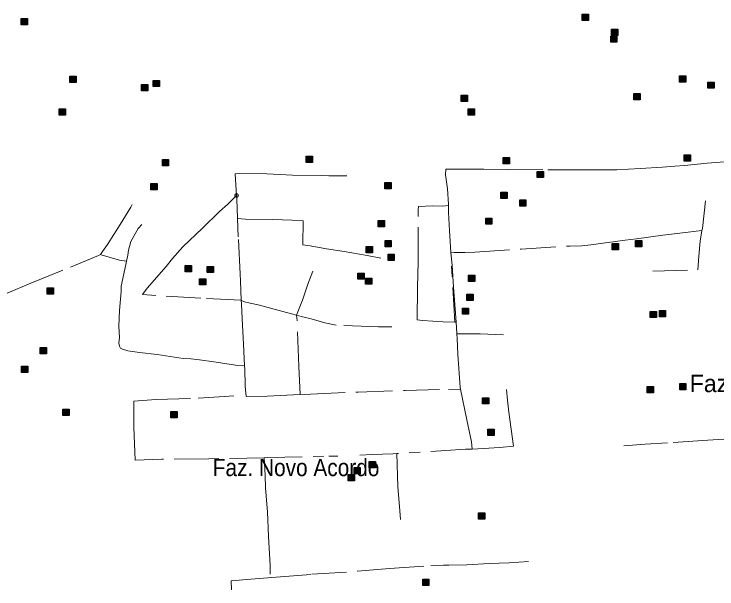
# Model space of a CAD drawing. Extents: x 393.5 to 446.9, y 8064.8 to 8120.4.
# Drawn here: x 418.49 to 425, y 8070.3 to 8075.61 of the extents above; entities that cross this region are included whole.
import ezdxf

# ---------------------------------------------------------------- set-up
doc = ezdxf.new("R2010")
doc.units = 0
doc.header["$LTSCALE"] = 0.064
doc.header["$PDMODE"] = 32
doc.header["$PDSIZE"] = 0.032
doc.linetypes.add('DOT_DASHED', pattern=[7.7, 5, -1.2, 0.3, -1.2])
doc.layers.add('2', color=7, linetype='Continuous', lineweight=25)
doc.layers.add('22', color=7, linetype='DOT_DASHED', lineweight=13)
doc.layers.add('61', color=7, linetype='Continuous')

msp = doc.modelspace()

# ---------------------------------------------------------------- hatches: boundary and pattern name
at = {"layer": '2'}
for points in [[(423.7495, 8075.6148), (423.8075, 8075.6148), (423.8075, 8075.5568), (423.7495, 8075.5568)], [(418.5591, 8075.573), (418.6171, 8075.573), (418.6171, 8075.515), (418.5591, 8075.515)], [(424.0194, 8075.4754), (424.0774, 8075.4754), (424.0774, 8075.4174), (424.0194, 8075.4174)], [(424.0124, 8075.4115), (424.0704, 8075.4115), (424.0704, 8075.3535), (424.0124, 8075.3535)], [(419.0076, 8075.0404), (419.0656, 8075.0404), (419.0656, 8074.9824), (419.0076, 8074.9824)], [(424.6491, 8075.0438), (424.7071, 8075.0438), (424.7071, 8074.9858), (424.6491, 8074.9858)], [(419.6731, 8074.9643), (419.7311, 8074.9643), (419.7311, 8074.9063), (419.6731, 8074.9063)], [(419.7799, 8075.0016), (419.8379, 8075.0016), (419.8379, 8074.9436), (419.7799, 8074.9436)], [(424.9126, 8074.9862), (424.9706, 8074.9862), (424.9706, 8074.9282), (424.9126, 8074.9282)], [(422.6299, 8074.8644), (422.6879, 8074.8644), (422.6879, 8074.8064), (422.6299, 8074.8064)], [(424.2267, 8074.8811), (424.2847, 8074.8811), (424.2847, 8074.8231), (424.2267, 8074.8231)], [(418.9099, 8074.7385), (418.9679, 8074.7385), (418.9679, 8074.6805), (418.9099, 8074.6805)], [(422.6932, 8074.7373), (422.7512, 8074.7373), (422.7512, 8074.6793), (422.6932, 8074.6793)], [(424.693, 8074.3134), (424.751, 8074.3134), (424.751, 8074.2554), (424.693, 8074.2554)], [(419.8649, 8074.2699), (419.9229, 8074.2699), (419.9229, 8074.2119), (419.8649, 8074.2119)], [(421.1945, 8074.2996), (421.2525, 8074.2996), (421.2525, 8074.2416), (421.1945, 8074.2416)], [(423.0179, 8074.289), (423.0759, 8074.289), (423.0759, 8074.231), (423.0179, 8074.231)], [(423.3316, 8074.1605), (423.3896, 8074.1605), (423.3896, 8074.1025), (423.3316, 8074.1025)], [(421.9236, 8074.0572), (421.9816, 8074.0572), (421.9816, 8073.9992), (421.9236, 8073.9992)], [(419.7583, 8074.0486), (419.8163, 8074.0486), (419.8163, 8073.9906), (419.7583, 8073.9906)], [(422.9957, 8073.9681), (423.0537, 8073.9681), (423.0537, 8073.9101), (422.9957, 8073.9101)], [(423.171, 8073.8981), (423.229, 8073.8981), (423.229, 8073.8401), (423.171, 8073.8401)], [(422.8561, 8073.7291), (422.9141, 8073.7291), (422.9141, 8073.6711), (422.8561, 8073.6711)], [(421.8619, 8073.706), (421.9199, 8073.706), (421.9199, 8073.648), (421.8619, 8073.648)], [(421.7494, 8073.4662), (421.8074, 8073.4662), (421.8074, 8073.4082), (421.7494, 8073.4082)], [(421.9245, 8073.5218), (421.9825, 8073.5218), (421.9825, 8073.4638), (421.9245, 8073.4638)], [(424.026, 8073.493), (424.084, 8073.493), (424.084, 8073.435), (424.026, 8073.435)], [(424.243, 8073.5209), (424.301, 8073.5209), (424.301, 8073.4629), (424.243, 8073.4629)], [(421.9528, 8073.3948), (422.0108, 8073.3948), (422.0108, 8073.3368), (421.9528, 8073.3368)], [(420.0762, 8073.2886), (420.1342, 8073.2886), (420.1342, 8073.2306), (420.0762, 8073.2306)], [(420.2788, 8073.2821), (420.3368, 8073.2821), (420.3368, 8073.2241), (420.2788, 8073.2241)], [(421.6727, 8073.2201), (421.7307, 8073.2201), (421.7307, 8073.1621), (421.6727, 8073.1621)], [(420.2081, 8073.168), (420.2661, 8073.168), (420.2661, 8073.11), (420.2081, 8073.11)], [(421.7453, 8073.1742), (421.8033, 8073.1742), (421.8033, 8073.1162), (421.7453, 8073.1162)], [(422.6964, 8073.1995), (422.7544, 8073.1995), (422.7544, 8073.1415), (422.6964, 8073.1415)], [(418.7995, 8073.0831), (418.8575, 8073.0831), (418.8575, 8073.0251), (418.7995, 8073.0251)], [(422.6822, 8073.0254), (422.7402, 8073.0254), (422.7402, 8072.9674), (422.6822, 8072.9674)], [(422.6403, 8072.8966), (422.6983, 8072.8966), (422.6983, 8072.8386), (422.6403, 8072.8386)], [(424.3771, 8072.8658), (424.4351, 8072.8658), (424.4351, 8072.8078), (424.3771, 8072.8078)], [(424.4628, 8072.8728), (424.5208, 8072.8728), (424.5208, 8072.8148), (424.4628, 8072.8148)], [(418.7344, 8072.5319), (418.7924, 8072.5319), (418.7924, 8072.4739), (418.7344, 8072.4739)], [(418.5621, 8072.3585), (418.6201, 8072.3585), (418.6201, 8072.3005), (418.5621, 8072.3005)], [(424.35, 8072.1697), (424.408, 8072.1697), (424.408, 8072.1117), (424.35, 8072.1117)], [(424.6508, 8072.198), (424.7088, 8072.198), (424.7088, 8072.14), (424.6508, 8072.14)], [(422.8281, 8072.0677), (422.8861, 8072.0677), (422.8861, 8072.0097), (422.8281, 8072.0097)], [(418.9453, 8071.9618), (419.0033, 8071.9618), (419.0033, 8071.9038), (418.9453, 8071.9038)], [(419.9442, 8071.9406), (420.0022, 8071.9406), (420.0022, 8071.8826), (419.9442, 8071.8826)], [(422.8755, 8071.7758), (422.9335, 8071.7758), (422.9335, 8071.7178), (422.8755, 8071.7178)], [(421.7778, 8071.4764), (421.8358, 8071.4764), (421.8358, 8071.4184), (421.7778, 8071.4184)], [(421.6377, 8071.4209), (421.6957, 8071.4209), (421.6957, 8071.3629), (421.6377, 8071.3629)], [(421.5846, 8071.3565), (421.6426, 8071.3565), (421.6426, 8071.2985), (421.5846, 8071.2985)], [(422.79, 8071.0016), (422.848, 8071.0016), (422.848, 8070.9436), (422.79, 8070.9436)], [(422.2733, 8070.3884), (422.3313, 8070.3884), (422.3313, 8070.3304), (422.2733, 8070.3304)]]:
    msp.add_hatch(color=256, dxfattribs=at).paths.add_polyline_path(points)

# ---------------------------------------------------------------- linework, layer by layer
for points in [[(423.7495, 8075.6148), (423.8075, 8075.6148), (423.8075, 8075.5568), (423.7495, 8075.5568)], [(418.5591, 8075.573), (418.6171, 8075.573), (418.6171, 8075.515), (418.5591, 8075.515)], [(424.0194, 8075.4754), (424.0774, 8075.4754), (424.0774, 8075.4174), (424.0194, 8075.4174)], [(424.0124, 8075.4115), (424.0704, 8075.4115), (424.0704, 8075.3535), (424.0124, 8075.3535)], [(419.0076, 8075.0404), (419.0656, 8075.0404), (419.0656, 8074.9824), (419.0076, 8074.9824)], [(424.6491, 8075.0438), (424.7071, 8075.0438), (424.7071, 8074.9858), (424.6491, 8074.9858)], [(419.6731, 8074.9643), (419.7311, 8074.9643), (419.7311, 8074.9063), (419.6731, 8074.9063)], [(419.7799, 8075.0016), (419.8379, 8075.0016), (419.8379, 8074.9436), (419.7799, 8074.9436)], [(424.9126, 8074.9862), (424.9706, 8074.9862), (424.9706, 8074.9282), (424.9126, 8074.9282)], [(422.6299, 8074.8644), (422.6879, 8074.8644), (422.6879, 8074.8064), (422.6299, 8074.8064)], [(424.2267, 8074.8811), (424.2847, 8074.8811), (424.2847, 8074.8231), (424.2267, 8074.8231)], [(418.9099, 8074.7385), (418.9679, 8074.7385), (418.9679, 8074.6805), (418.9099, 8074.6805)], [(422.6932, 8074.7373), (422.7512, 8074.7373), (422.7512, 8074.6793), (422.6932, 8074.6793)], [(424.693, 8074.3134), (424.751, 8074.3134), (424.751, 8074.2554), (424.693, 8074.2554)], [(419.8649, 8074.2699), (419.9229, 8074.2699), (419.9229, 8074.2119), (419.8649, 8074.2119)], [(421.1945, 8074.2996), (421.2525, 8074.2996), (421.2525, 8074.2416), (421.1945, 8074.2416)], [(423.0179, 8074.289), (423.0759, 8074.289), (423.0759, 8074.231), (423.0179, 8074.231)], [(423.3316, 8074.1605), (423.3896, 8074.1605), (423.3896, 8074.1025), (423.3316, 8074.1025)], [(421.9236, 8074.0572), (421.9816, 8074.0572), (421.9816, 8073.9992), (421.9236, 8073.9992)], [(419.7583, 8074.0486), (419.8163, 8074.0486), (419.8163, 8073.9906), (419.7583, 8073.9906)], [(422.9957, 8073.9681), (423.0537, 8073.9681), (423.0537, 8073.9101), (422.9957, 8073.9101)], [(423.171, 8073.8981), (423.229, 8073.8981), (423.229, 8073.8401), (423.171, 8073.8401)], [(422.8561, 8073.7291), (422.9141, 8073.7291), (422.9141, 8073.6711), (422.8561, 8073.6711)], [(421.8619, 8073.706), (421.9199, 8073.706), (421.9199, 8073.648), (421.8619, 8073.648)], [(421.7494, 8073.4662), (421.8074, 8073.4662), (421.8074, 8073.4082), (421.7494, 8073.4082)], [(421.9245, 8073.5218), (421.9825, 8073.5218), (421.9825, 8073.4638), (421.9245, 8073.4638)], [(424.026, 8073.493), (424.084, 8073.493), (424.084, 8073.435), (424.026, 8073.435)], [(424.243, 8073.5209), (424.301, 8073.5209), (424.301, 8073.4629), (424.243, 8073.4629)], [(421.9528, 8073.3948), (422.0108, 8073.3948), (422.0108, 8073.3368), (421.9528, 8073.3368)], [(420.0762, 8073.2886), (420.1342, 8073.2886), (420.1342, 8073.2306), (420.0762, 8073.2306)], [(420.2788, 8073.2821), (420.3368, 8073.2821), (420.3368, 8073.2241), (420.2788, 8073.2241)], [(421.6727, 8073.2201), (421.7307, 8073.2201), (421.7307, 8073.1621), (421.6727, 8073.1621)], [(420.2081, 8073.168), (420.2661, 8073.168), (420.2661, 8073.11), (420.2081, 8073.11)], [(421.7453, 8073.1742), (421.8033, 8073.1742), (421.8033, 8073.1162), (421.7453, 8073.1162)], [(422.6964, 8073.1995), (422.7544, 8073.1995), (422.7544, 8073.1415), (422.6964, 8073.1415)], [(418.7995, 8073.0831), (418.8575, 8073.0831), (418.8575, 8073.0251), (418.7995, 8073.0251)], [(422.6822, 8073.0254), (422.7402, 8073.0254), (422.7402, 8072.9674), (422.6822, 8072.9674)], [(422.6403, 8072.8966), (422.6983, 8072.8966), (422.6983, 8072.8386), (422.6403, 8072.8386)], [(424.3771, 8072.8658), (424.4351, 8072.8658), (424.4351, 8072.8078), (424.3771, 8072.8078)], [(424.4628, 8072.8728), (424.5208, 8072.8728), (424.5208, 8072.8148), (424.4628, 8072.8148)], [(418.7344, 8072.5319), (418.7924, 8072.5319), (418.7924, 8072.4739), (418.7344, 8072.4739)], [(418.5621, 8072.3585), (418.6201, 8072.3585), (418.6201, 8072.3005), (418.5621, 8072.3005)], [(424.35, 8072.1697), (424.408, 8072.1697), (424.408, 8072.1117), (424.35, 8072.1117)], [(424.6508, 8072.198), (424.7088, 8072.198), (424.7088, 8072.14), (424.6508, 8072.14)], [(422.8281, 8072.0677), (422.8861, 8072.0677), (422.8861, 8072.0097), (422.8281, 8072.0097)], [(418.9453, 8071.9618), (419.0033, 8071.9618), (419.0033, 8071.9038), (418.9453, 8071.9038)], [(419.9442, 8071.9406), (420.0022, 8071.9406), (420.0022, 8071.8826), (419.9442, 8071.8826)], [(422.8755, 8071.7758), (422.9335, 8071.7758), (422.9335, 8071.7178), (422.8755, 8071.7178)], [(421.7778, 8071.4764), (421.8358, 8071.4764), (421.8358, 8071.4184), (421.7778, 8071.4184)], [(421.6377, 8071.4209), (421.6957, 8071.4209), (421.6957, 8071.3629), (421.6377, 8071.3629)], [(421.5846, 8071.3565), (421.6426, 8071.3565), (421.6426, 8071.2985), (421.5846, 8071.2985)], [(422.79, 8071.0016), (422.848, 8071.0016), (422.848, 8070.9436), (422.79, 8070.9436)], [(422.2733, 8070.3884), (422.3313, 8070.3884), (422.3313, 8070.3304), (422.2733, 8070.3304)]]:
    msp.add_lwpolyline(points, close=True, dxfattribs=at)
at = {"layer": '22'}
for p, q in [((420.5604, 8073.7257), (420.5604, 8073.7261)), ((420.5604, 8073.7257), (420.5608, 8073.7257)), ((420.5943, 8072.9693), (420.5937, 8072.9693)), ((420.5943, 8072.9693), (420.5943, 8072.9701)), ((422.5896, 8072.6596), (422.5907, 8072.6596)), ((420.8065, 8071.5123), (420.8059, 8071.5123))]:
    msp.add_line(p, q, dxfattribs=at)
for points in [[(422.5115, 8073.8435), (422.5115, 8073.847), (422.5109, 8073.8561), (422.5013, 8073.9993), (422.4847, 8074.1279), (422.4869, 8074.1793), (422.5631, 8074.1814), (422.8391, 8074.1814), (423.0649, 8074.1787), (423.432, 8074.175), (423.7472, 8074.1734), (423.9879, 8074.1745), (424.0682, 8074.1745), (424.2868, 8074.1873), (424.4933, 8074.198), (424.6048, 8074.2077), (424.6941, 8074.215), (424.9062, 8074.2355), (425.1447, 8074.2548), (425.2452, 8074.258), (425.2904, 8074.2633)], [(420.5516, 8073.9375), (420.5396, 8074.1379), (420.5776, 8074.1415), (420.8327, 8074.1361), (421.0679, 8074.1252), (421.3392, 8074.1219)], [(421.3392, 8074.1219), (421.4059, 8074.1204), (421.5704, 8074.1182)], [(420.5937, 8072.9693), (420.2199, 8072.9868), (419.8056, 8073.0121), (419.6816, 8073.0211), (419.7233, 8073.0807), (419.8988, 8073.2814), (419.957, 8073.3545), (420.0535, 8073.4626), (420.2362, 8073.6361), (420.3936, 8073.7898), (420.4714, 8073.8567), (420.5516, 8073.9375)], [(420.5604, 8073.7261), (420.5536, 8073.9024), (420.5518, 8073.9346), (420.5516, 8073.9375)], [(424.8562, 8073.6127), (424.8619, 8073.6316), (424.8887, 8073.8885)], [(419.5848, 8073.8528), (419.5725, 8073.829), (419.4742, 8073.669), (419.3582, 8073.483), (419.3111, 8073.4198), (419.2936, 8073.3913), (419.2984, 8073.3899)], [(422.5717, 8072.7662), (422.4624, 8072.7704), (422.2728, 8072.7825), (422.2227, 8072.7877), (422.2263, 8073.0862), (422.231, 8073.323), (422.2317, 8073.8045), (422.2353, 8073.8358), (422.3641, 8073.841), (422.4553, 8073.8392), (422.5115, 8073.8433)], [(422.5717, 8072.7662), (422.5338, 8073.4112), (422.5215, 8073.6122), (422.5107, 8073.7805), (422.5115, 8073.8434), (422.5115, 8073.8435)], [(419.6747, 8073.6691), (419.6421, 8073.6329), (419.5734, 8073.5118), (419.5517, 8073.4318)], [(420.5943, 8072.9701), (420.5868, 8073.1486), (420.5852, 8073.2111), (420.5674, 8073.5541), (420.5604, 8073.7257)], [(420.5608, 8073.7257), (420.6352, 8073.7197), (420.8879, 8073.7143), (421.0651, 8073.708), (421.1679, 8073.7016), (421.1657, 8073.4808), (421.2336, 8073.4723), (421.3845, 8073.4447), (421.5464, 8073.4192), (421.7586, 8073.3832), (421.8868, 8073.3564)], [(424.4021, 8073.2386), (424.8194, 8073.2505), (424.8266, 8073.3772), (424.8409, 8073.516), (424.8562, 8073.6127)], [(424.4952, 8073.5694), (424.5751, 8073.5803), (424.8553, 8073.6126), (424.8562, 8073.6127)], [(422.6645, 8073.4113), (422.7557, 8073.4147), (423.1857, 8073.4424), (423.6343, 8073.4693), (423.747, 8073.4727), (423.8274, 8073.4797), (424.0564, 8073.5109), (424.1458, 8073.5231), (424.2513, 8073.5369), (424.4952, 8073.5694)], [(419.5517, 8073.4318), (419.5444, 8073.3852), (419.5324, 8073.3299)], [(422.5579, 8073.0883), (422.5454, 8073.2925), (422.534, 8073.4078), (422.536, 8073.4079)], [(422.536, 8073.4079), (422.5644, 8073.4095), (422.6645, 8073.4113)], [(418.3468, 8072.7561), (418.3481, 8072.7622), (418.3537, 8072.9973), (418.4279, 8073.0353), (418.6468, 8073.1257), (419.0159, 8073.2757), (419.2736, 8073.383), (419.2936, 8073.3913)], [(419.2984, 8073.3899), (419.4691, 8073.3389), (419.5314, 8073.33), (419.5324, 8073.3299)], [(419.5324, 8073.3299), (419.5252, 8073.2992), (419.4833, 8073.0991), (419.4834, 8073.0501), (419.4683, 8072.8747), (419.4606, 8072.7279), (419.4667, 8072.6242), (419.4627, 8072.572), (419.4667, 8072.5427), (419.4765, 8072.5271), (419.4962, 8072.5153), (419.5458, 8072.4998), (419.6526, 8072.4853), (419.8154, 8072.4672), (420.0578, 8072.4311), (420.1286, 8072.4258)], [(421.1066, 8072.8298), (421.1605, 8072.9695), (421.2108, 8073.1179), (421.2571, 8073.237)], [(422.5841, 8072.7658), (422.574, 8072.8887), (422.5579, 8073.0883)], [(420.6246, 8072.3615), (420.6138, 8072.564), (420.6018, 8072.7983), (420.5977, 8072.935), (420.5943, 8072.9693)], [(421.1065, 8072.8298), (421.0583, 8072.8435), (420.7506, 8072.9252), (420.6782, 8072.9428), (420.6259, 8072.9545), (420.5981, 8072.9675), (420.5943, 8072.9693)], [(421.9877, 8072.7241), (421.863, 8072.7241), (421.4714, 8072.739), (421.3686, 8072.7602), (421.3057, 8072.779), (421.2292, 8072.8005), (421.1487, 8072.8181), (421.1066, 8072.8298), (421.1065, 8072.8298)], [(421.1397, 8072.0966), (421.1286, 8072.3573), (421.1106, 8072.7829), (421.1066, 8072.8298)], [(422.5841, 8072.7658), (422.5828, 8072.7658), (422.5717, 8072.7662)], [(422.5841, 8072.7658), (422.5841, 8072.7654), (422.5894, 8072.6611), (422.5896, 8072.6596)], [(422.6222, 8072.1471), (422.619, 8072.163), (422.5976, 8072.471), (422.5907, 8072.6142), (422.5896, 8072.6596)], [(422.5907, 8072.6596), (422.8037, 8072.6567), (423.0196, 8072.65)], [(420.1286, 8072.4258), (420.2074, 8072.4172), (420.3397, 8072.399), (420.5631, 8072.3653), (420.6246, 8072.3615)], [(420.6409, 8072.0792), (420.6306, 8072.1741), (420.6266, 8072.3361), (420.6248, 8072.3594), (420.6246, 8072.3615)], [(421.1397, 8072.0966), (421.235, 8072.1011), (421.6755, 8072.1201), (422.1096, 8072.1338), (422.5111, 8072.1449), (422.6222, 8072.1471)], [(422.6222, 8072.1471), (422.6808, 8071.8614), (422.7256, 8071.661), (422.7325, 8071.5926)], [(422.7325, 8071.5926), (422.9872, 8071.606), (423.114, 8071.6191), (423.0709, 8071.9332), (423.0574, 8072.0457), (423.0493, 8072.1426)], [(420.8059, 8071.5123), (420.295, 8071.503), (419.8596, 8071.4982), (419.6123, 8071.4915), (419.6013, 8071.7951), (419.6013, 8072.0349), (419.8038, 8072.0503), (420.1958, 8072.0635), (420.4409, 8072.0788), (420.527, 8072.0838)], [(421.1397, 8072.0966), (420.8334, 8072.0818), (420.6409, 8072.0792)], [(425.6538, 8071.6448), (425.6447, 8071.7206), (425.0617, 8071.6837), (424.9111, 8071.6759), (424.5378, 8071.6506), (424.3331, 8071.637), (424.1344, 8071.6234)], [(422.7325, 8071.5926), (422.6683, 8071.5906), (422.0333, 8071.5519)], [(420.8065, 8071.5123), (420.8385, 8071.5146), (421.4033, 8071.5266), (421.4873, 8071.5281)], [(422.0333, 8071.5519), (421.9975, 8071.5498), (421.8058, 8071.5428), (421.6915, 8071.5367)], [(422.0333, 8071.5519), (422.0425, 8071.242), (422.0572, 8071.0607), (422.068, 8070.9403)], [(420.8635, 8070.4371), (420.8628, 8070.5172), (420.8457, 8070.7831), (420.8371, 8071.0136), (420.8191, 8071.2305), (420.8145, 8071.3514), (420.8065, 8071.5123)], [(422.4685, 8070.5202), (422.5143, 8070.519), (422.6816, 8070.5232), (422.888, 8070.5338), (423.0728, 8070.5422), (423.251, 8070.5528)], [(420.0245, 8069.5778), (420.2419, 8069.6435), (420.5178, 8069.7284), (420.5153, 8069.8714), (420.5019, 8070.3755), (420.6843, 8070.3904), (420.9188, 8070.4071), (421.2487, 8070.4348), (421.6711, 8070.4627), (421.9652, 8070.4869), (422.3475, 8070.5146), (422.4664, 8070.5201), (422.4685, 8070.5202)]]:
    msp.add_lwpolyline(points, dxfattribs=at)
msp.add_point((420.5516, 8073.9375), dxfattribs=at)

# ---------------------------------------------------------------- texts
at = {"layer": '61'}
msp.add_text('Faz. Sto. Antônio', height=0.16, dxfattribs=at).set_placement((424.7437, 8072.1192))
at = {"layer": '61', "width": 0.9}
msp.add_text('Faz. Novo Acordo', height=0.16, dxfattribs=at).set_placement((420.3311, 8071.3422))

doc.saveas('drawing.dxf')
